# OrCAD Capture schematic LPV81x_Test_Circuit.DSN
size A; title: LPV811/LPV812 Precision 425 nA Nanopower Operational; rev: 1.1; note: Datasheet: SNOSD33B  EVM: N/A
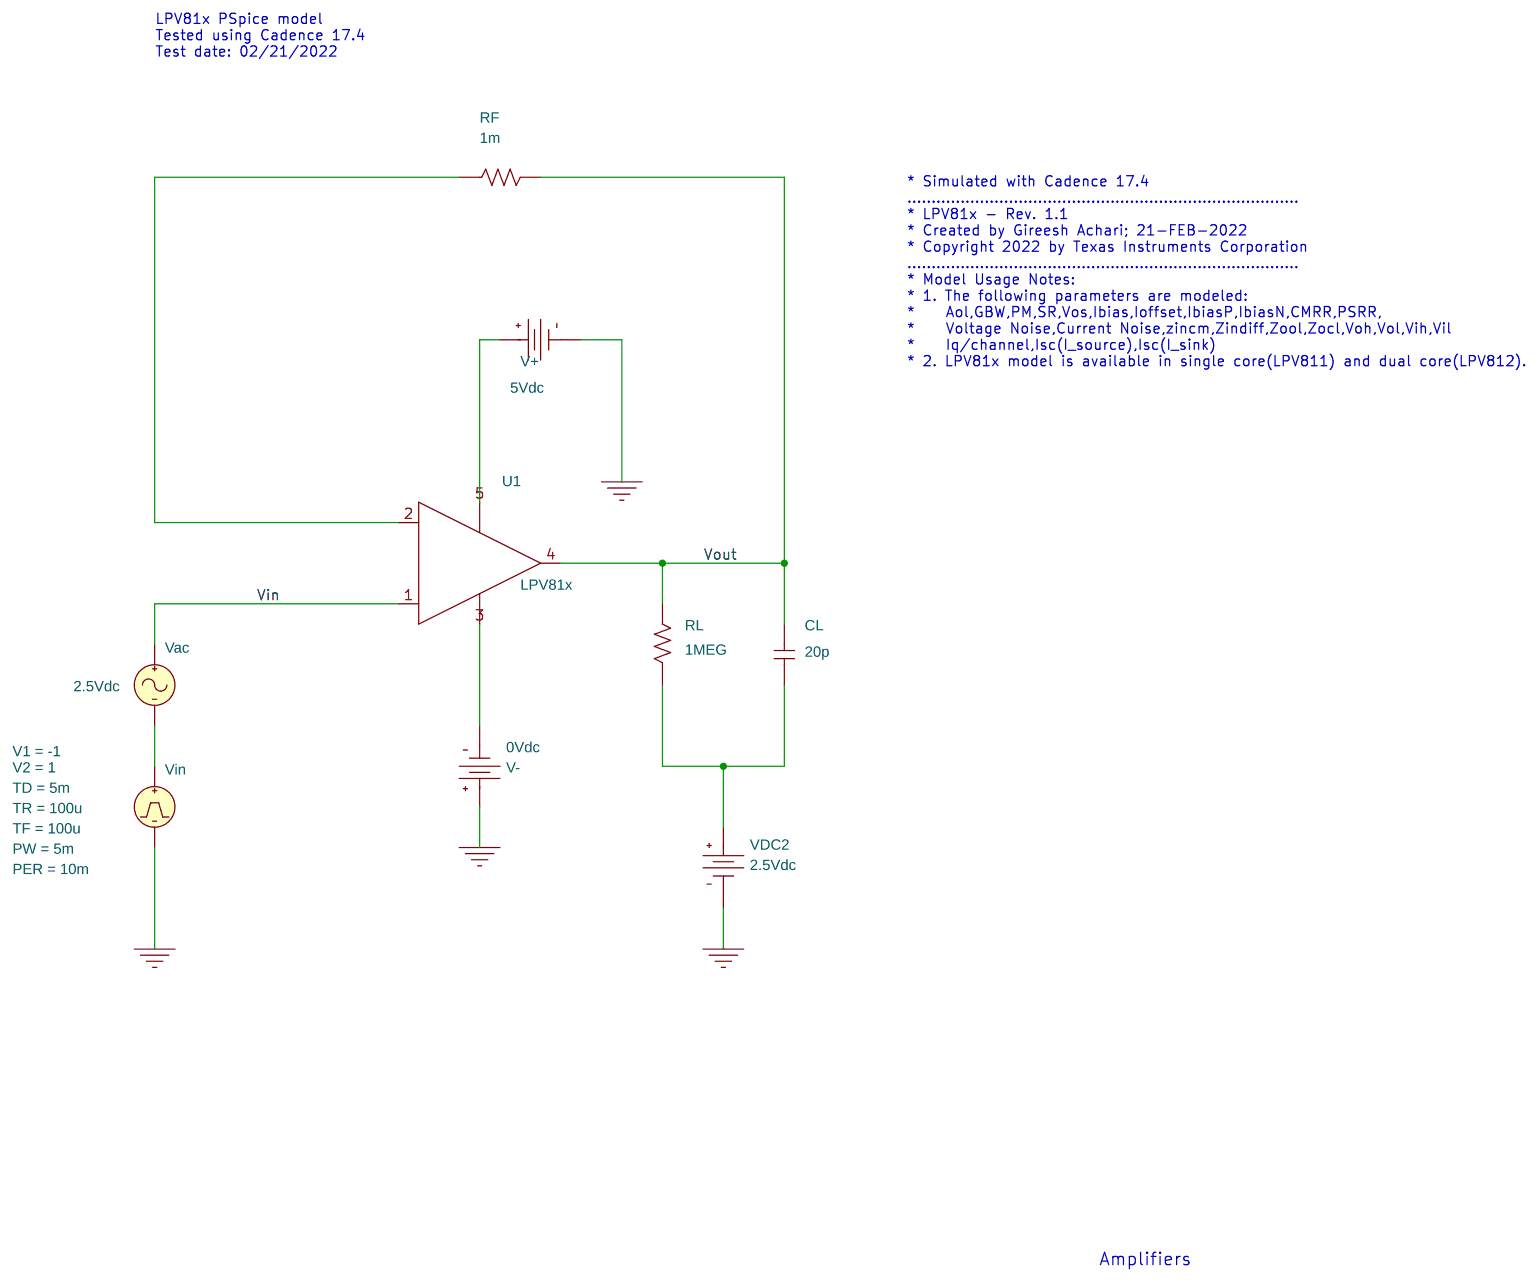
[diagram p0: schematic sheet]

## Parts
CL  20p  [cap196]
RF  1m  [AXRC05]
RL  1MEG  [AXRC05]
U1  LPV81x
V+  VDC
V-  VDC
Vac  VAC
VDC2  VDC
Vin  VPULSE

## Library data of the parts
CL = C
RF RL = R
U1 = LPV81x
V+ = VDC: DC: 5Vdc
V- = VDC: DC: 0Vdc
Vac = VAC: DC: 2.5Vdc
VDC2 = VDC: DC: 2.5Vdc
Vin = VPULSE: PER: 10m; PW: 5m; TD: 5m; TF: 100u; TR: 100u; V1: -1; V2: 1

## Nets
Vin: U1.1(+) Vac.1(+)
0: V+.1(-) V-.0(+) VDC2.1(-) Vin.2(-)
Vout: CL.1 RF.2 RL.2 U1.4(OUT)
N46310: RF.1 U1.2(-)
N46434: U1.5(V+) V+.0(+)
N46592: U1.3(V-) V-.1(-)
N48518: CL.2 RL.1 VDC2.0(+)
N49956: Vac.2(-) Vin.1(+)

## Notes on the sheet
- LPV81x PSpice model
  Tested using Cadence 17.4
  Test date: 02/21/2022
- * Simulated with Cadence 17.4
  .................................................................................
  * LPV81x - Rev. 1.1
  * Created by Gireesh Achari; 21-FEB-2022
  * Copyright 2022 by Texas Instruments Corporation
  .................................................................................
  * Model Usage Notes:
  * 1. The following parameters are modeled:
  *    Aol,GBW,PM,SR,Vos,Ibias,Ioffset,IbiasP,IbiasN,CMRR,PSRR,
  *    Voltage Noise,Current Noise,zincm,Zindiff,Zool,Zocl,Voh,Vol,Vih,Vil
  *    Iq/channel,Isc(I_source),Isc(I_sink)
  * 2. LPV81x model is available in single core(LPV811) and dual core(LPV812).
- Amplifiers
